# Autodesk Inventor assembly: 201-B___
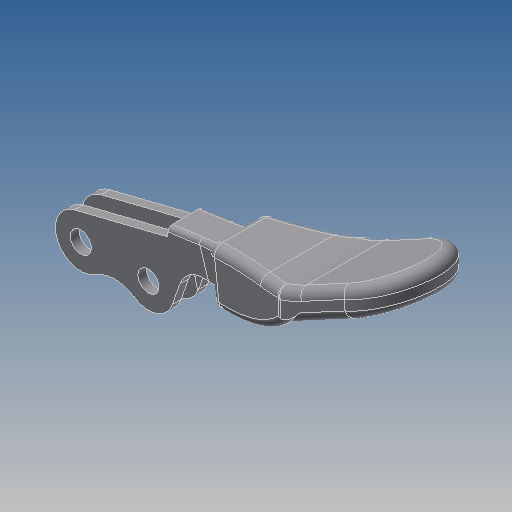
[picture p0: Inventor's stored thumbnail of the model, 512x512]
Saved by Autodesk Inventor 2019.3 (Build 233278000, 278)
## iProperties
Created: 2010-06
Part Number: 201-B___
Material: Ogólny
Document SubType Name: Assembly
Designer: CADENGINEERING4
Author: CADENGINEERING4
Revision Number: ANY
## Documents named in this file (3)
- E:\STRONA\Horizontal toggle clamp\CH-201-BSI\201-B___.iam
- E:\STRONA\Horizontal toggle clamp\CH-201-BSI\201-B-03___.ipt
- E:\STRONA\Horizontal toggle clamp\CH-201-BSI\201-B-05___.ipt
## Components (2 placed, 2 different names)
1. 201-B-03_??_14
2. 201-B-05_??_15
